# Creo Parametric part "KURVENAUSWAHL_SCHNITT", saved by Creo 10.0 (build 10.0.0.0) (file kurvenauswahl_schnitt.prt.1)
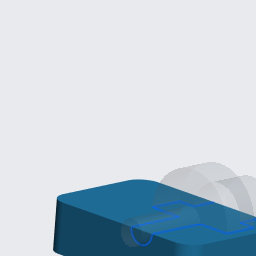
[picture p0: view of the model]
Materials in the file: S235JRG2

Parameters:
  BENENNUNG = "XXX"
  DATUM = "XX.XX.XX"
  ERSTELLER = "ARINDA"
  TEILETYP = "Fertigungsteil"
  PTC_MASTER_MATERIAL = "S235JRG2"
  SELECT_EN_NAME = "S235JRG2"
  SELECT_DIN_NAME = "RSt37-2"
  SELECT_DIN_NUMBER = "1.0038"
  SELECT_ASTM_NAME = "A 283 M Grade 2"
  MATERIAL_GROUP = "ME_ST_Baustahl"
  STANDARD_EN_DELIVERYSPEC = "DIN EN 10025"
  STANDARD_DIN_DELIVERYSPEC = "DIN 17100"

Other parameters: MASSE

Created from: KURVENAUSWAHL.PRT

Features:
  1. coordinate system
  2. datum plane "T_RECHTS_Y-Z"
  3. datum plane "T_OBEN_X-Z"
  4. datum plane "T_VORNE_X-Y"
  5. datum axis
  6. datum axis
  7. datum axis
  8. protrusion
  9. round
  10. revolve "Drehen 1"
  11. curve "Schneiden 1"

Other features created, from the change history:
  sketch "Skizze 2"
  curve "Kurve 2"
  extrusion "Profil 2" (2 times)
  datum plane "DTM1" (2 times)
  sketch "Skizze 3"
  curve "Kurve 1"

Other named items: T_BASIC, T_X-ACHSE, T_Y-ACHSE, T_Z-ACHSE

Layers: 00_STD-ACHSEN, 00_STD-EBENEN, 00_STD-KOORDSYS, 01_ACHSEN, 01_EBENEN, 01_KURVEN, KURVENELEMENTE, VOLUMENGEOMETRIE

Surfaces: 10 plane, 10 cylinder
